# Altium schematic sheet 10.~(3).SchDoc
size 398 x 287 mm
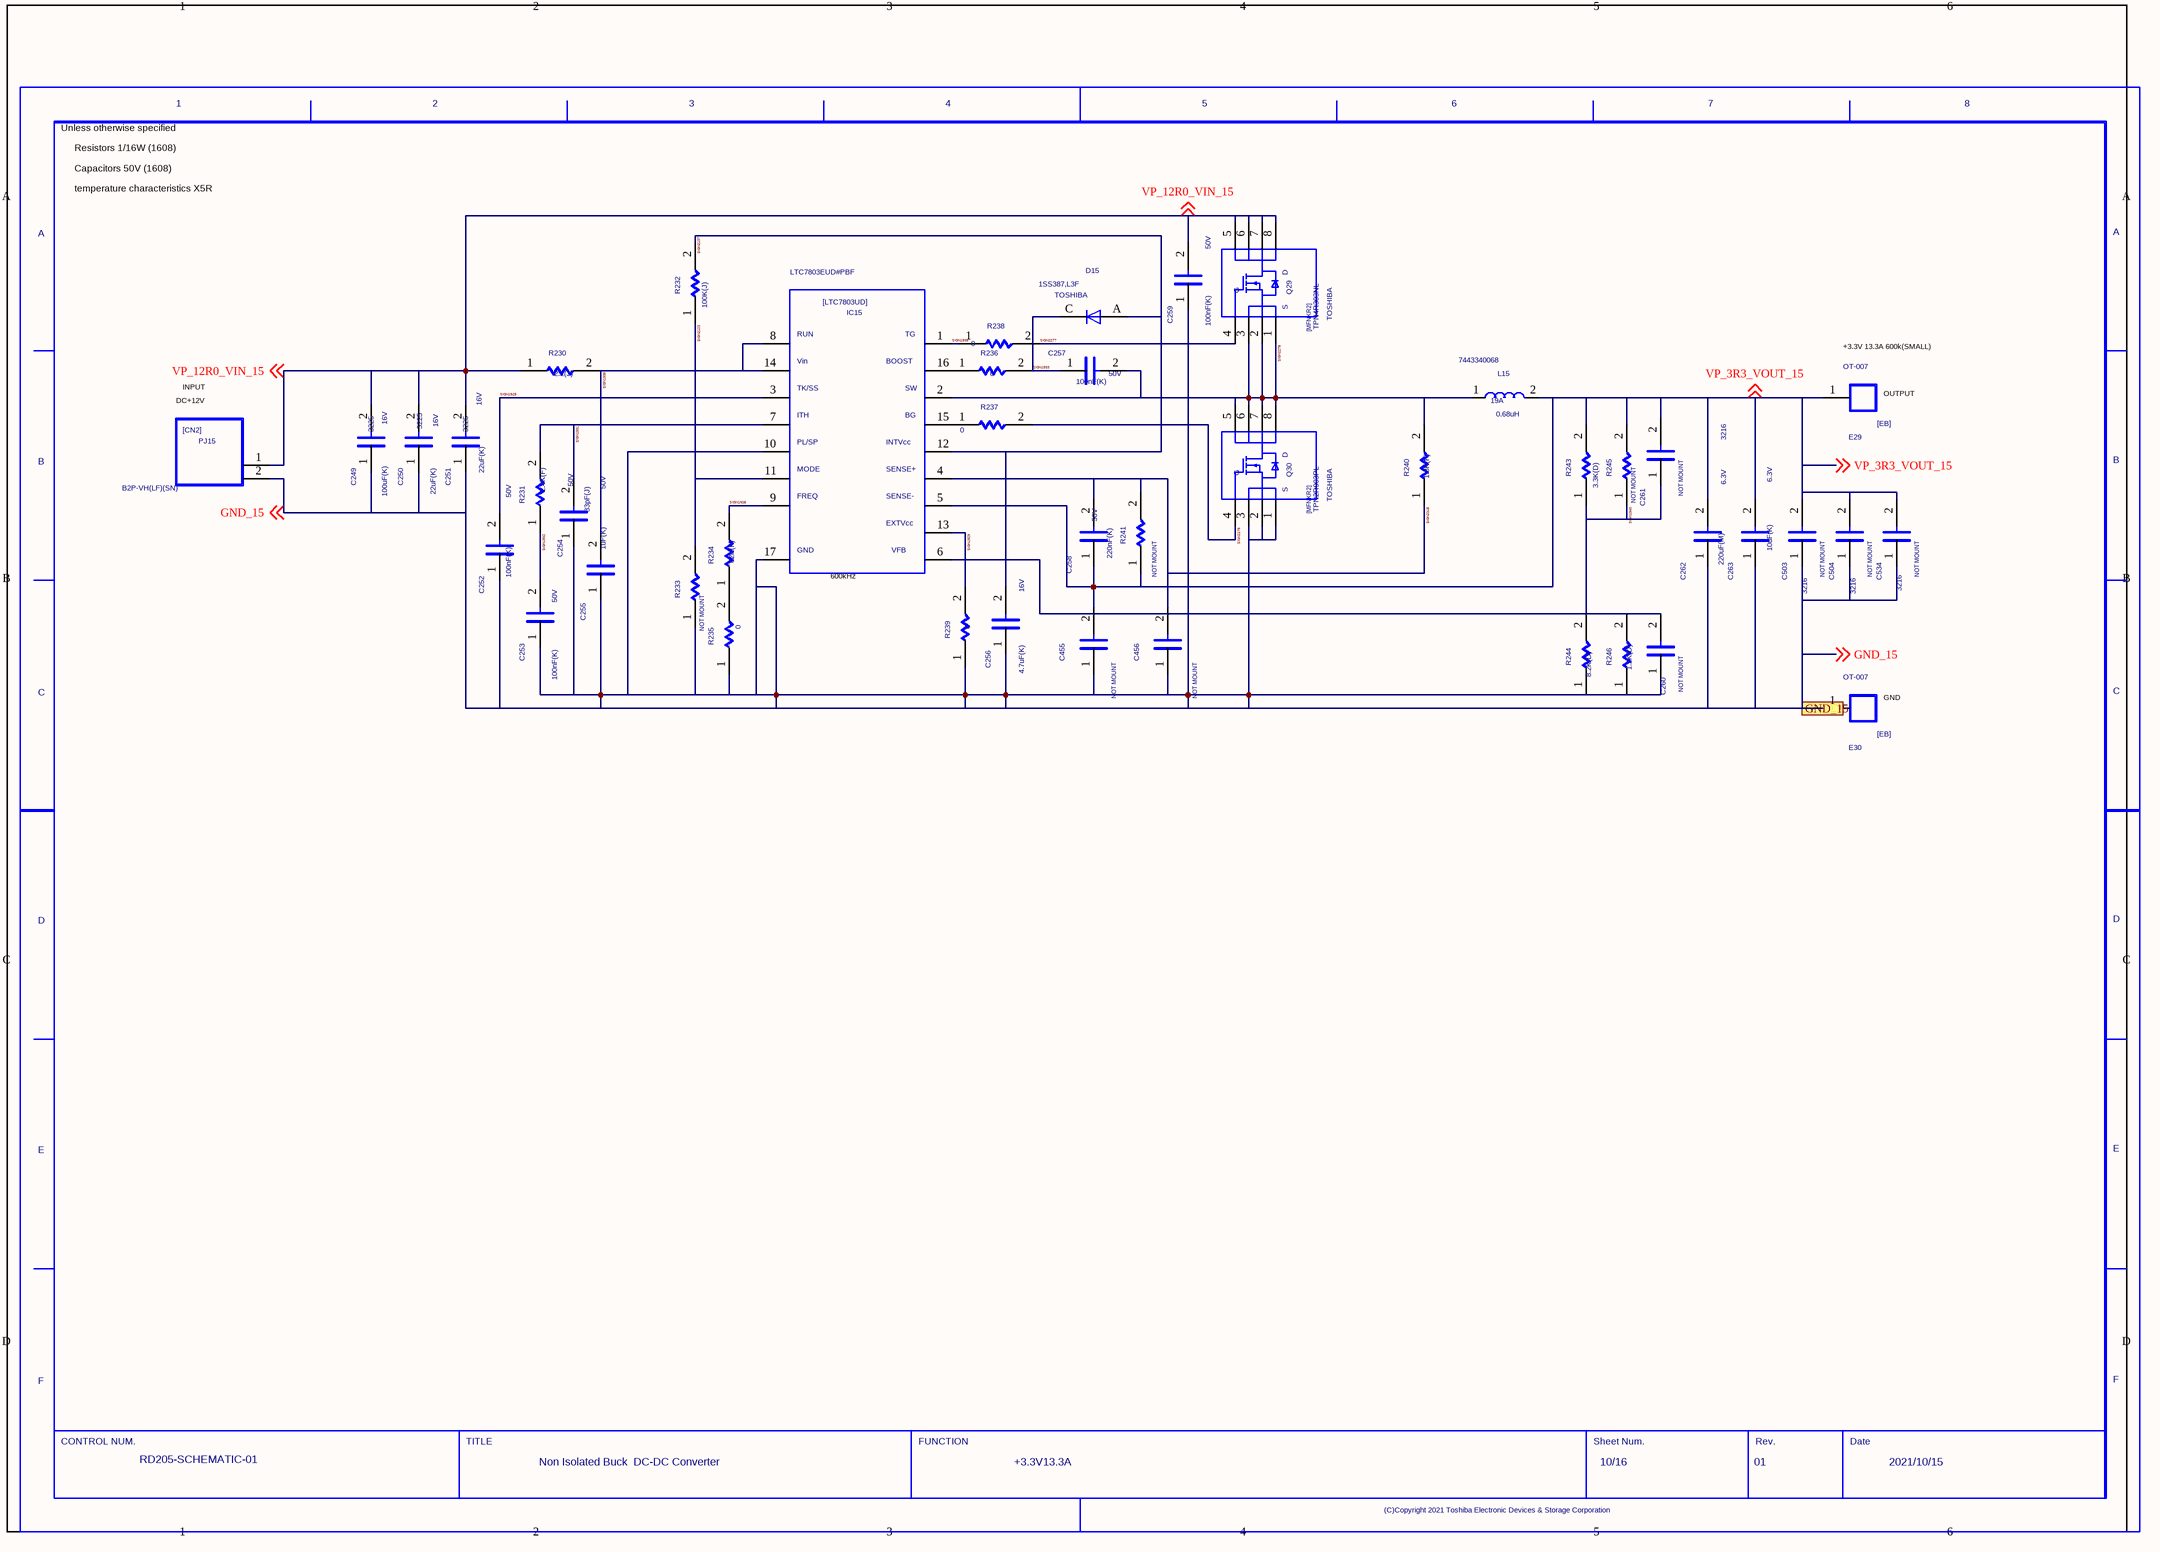
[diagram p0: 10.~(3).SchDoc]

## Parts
C249  SIZECODESMD: 3225  VAL2: 16V  VAL1: 100uF(K)  (hidden comment: C)
C250  SIZECODESMD: 3225  VAL2: 16V  VAL1: 22uF(K)  (hidden comment: C)
C251  SIZECODESMD: 3225  VAL2: 16V  VAL1: 22uF(K)  (hidden comment: C)
C252  VAL2: 50V  VAL1: 100nF(K)  (hidden comment: C)
C253  VAL2: 50V  VAL1: 100nF(K)  (hidden comment: C)
C254  VAL2: 50V  VAL1: 33pF(J)  (hidden comment: C)
C255  VAL2: 50V  VAL1: 1uF(K)  (hidden comment: C)
C256  VAL2: 16V  VAL1: 4.7uF(K)  (hidden comment: C)
C257  VAL2: 50V  VAL1: 100nF(K)  (hidden comment: C)
C258  VAL2: 50V  VAL1: 220nF(K)  (hidden comment: C)
C259  VAL2: 50V  VAL1: 100nF(K)  (hidden comment: C)
C260  NOTMOUNT: NOT MOUNT  (hidden comment: C)
C261  NOTMOUNT: NOT MOUNT  (hidden comment: C)
C262  SIZECODESMD: 3216  VAL2: 6.3V  VAL1: 220uF(M)  (hidden comment: C)
C263  VAL2: 6.3V  VAL1: 10uF(K)  (hidden comment: C)
C455  NOTMOUNT: NOT MOUNT  (hidden comment: C)
C456  NOTMOUNT: NOT MOUNT  (hidden comment: C)
C503  NOTMOUNT: NOT MOUNT  SIZECODESMD: 3216  (hidden comment: C)
C504  NOTMOUNT: NOT MOUNT  SIZECODESMD: 3216  (hidden comment: C)
C534  NOTMOUNT: NOT MOUNT  SIZECODESMD: 3216  (hidden comment: C)
D15  USERCOMPTEXT3: TOSHIBA  VAL3: 1SS387,L3F  (hidden comment: D)
E29  VAL3: OT-007  (hidden comment: EB)
E30  VAL3: OT-007  (hidden comment: EB)
IC15  VAL3: LTC7803EUD#PBF  (hidden comment: LTC7803UD)
L15  VAL3: 7443340068  VAL2: 19A  VAL1: 0.68uH  (hidden comment: L)
PJ15  VAL3: B2P-VH(LF)(SN)  (hidden comment: CN2)
Q29  USERCOMPTEXT3: TOSHIBA  VAL3: TPN4R303NL  (hidden comment: MFNKR2)
Q30  USERCOMPTEXT3: TOSHIBA  VAL3: TPN2R903PL  (hidden comment: MFNKR2)
R230  VAL1: 2.2(J)  (hidden comment: R)
R231  VAL1: 2.4K(F)  (hidden comment: R)
R232  VAL1: 100K(J)  (hidden comment: R)
R233  NOTMOUNT: NOT MOUNT  (hidden comment: R)
R234  VAL1: 62K(F)  (hidden comment: R)
R235  VAL1: 0  (hidden comment: R)
R236  VAL1: 0  (hidden comment: R)
R237  VAL1: 0  (hidden comment: R)
R238  VAL1: 0  (hidden comment: R)
R239  VAL1: 0  (hidden comment: R)
R240  VAL1: 1.8K(F)  (hidden comment: R)
R241  NOTMOUNT: NOT MOUNT  (hidden comment: R)
R243  VAL1: 3.3K(D)  (hidden comment: R)
R244  VAL1: 8.2K(D)  (hidden comment: R)
R245  NOTMOUNT: NOT MOUNT  (hidden comment: R)
R246  VAL1: 1.2K(D)  (hidden comment: R)
U?  DATE: 2021/10/15  SHEETNUMBER: 10/16  TITLE: Non Isolated Buck / DC-DC Converter  REVISION: 01  DRAWINGNUMBER: RD205-SCHEMATIC-01  FUNCTION: +3.3V13.3A  (hidden comment: WAKU_DEF100)

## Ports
GND_15

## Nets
GND_15: C249.1 C250.1 C251.1 C252.1 C253.1 C254.1 C255.1 C256.1 C259.1 C260.1 C262.1 C263.1 C455.1 C456.1 C503.1 C504.1 C534.1 E30.1 IC15.10 IC15.17 PJ15.2 Q30.1 Q30.2 Q30.3 R233.1 R235.1 R239.1 R244.1 R246.1 ; off-sheet GND_15, port GND_15
SIGN1928: C252.2 IC15.3
SIGN1929: IC15.13 R239.2
SIGN1931: C254.2 IC15.7 R231.2
SIGN1932: C253.2 R231.1
SIGN1933: C257.1 D15.C R236.2
SIGN1935: IC15.1 R238.1
SIGN1936: C255.2 IC15.8 IC15.14 R230.2
SIGN1938: IC15.9 R234.2
SIGN1940: C260.2 C261.1 IC15.6 R243.1 R244.2 R245.1 R246.2
SIGN2123: IC15.11 R232.1 R233.2
SIGN2137: C256.2 D15.A IC15.12 R232.2
SIGN2276: Q30.4 R237.2
SIGN2277: Q29.4 R238.2
SIGN2278: C257.2 IC15.2 L15.1 Q29.1 Q29.2 Q29.3 Q30.5 Q30.6 Q30.7 Q30.8 R240.2
SIGN2315: C258.2 C456.2 IC15.4 R240.1 R241.2
VP_3R3_VOUT_15: C258.1 C261.2 C262.2 C263.2 C455.2 C503.2 C504.2 C534.2 E29.1 IC15.5 L15.2 R241.1 R243.2 R245.2 ; off-sheet VP_3R3_VOUT_15
VP_12R0_VIN_15: C249.2 C250.2 C251.2 C259.2 PJ15.1 Q29.5 Q29.6 Q29.7 Q29.8 R230.1 ; off-sheet VP_12R0_VIN_15
NetIC15_15: IC15.15 R237.1
NetIC15_16: IC15.16 R236.1
NetR234_1: R234.1 R235.2

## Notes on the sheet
- Unless otherwise specified
- Resistors 1/16W (1608)
- Capacitors 50V (1608)
- temperature characteristics X5R
- DC+12V
- INPUT
- (near E29) +3.3V 13.3A 600k(SMALL)
- (near E29) OUTPUT
- (near IC15) 600kHz
- (near E30) GND

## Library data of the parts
C249 = C: SQ_PART_MODEL: CON_100n; FNPARTSNAMEG: CHIP CERAMIC CAPACITOR (3225); USEINPARTSLIST: YES; OriginalSymbolOrigin: (2540,7620); MFSOLDERINGPROP: .; TEMPCHARACTERI2: B; MFFORMINGDIVP: KC; OUMECLASSIFICATION: セラミックコンデンサ; MFMOUNTSYMBOLP: 90; CDMASTERCADCELG: DC903A; PCODE: P03276001115; FNCLASSCODEG: P03-03; MAXGCOUNT: 1; RATEDVOLTAGE: 250; COMPONENTNAME: G36030160049; OUMEMAKER: KYC 京セラ; MFPACKAGEMETHOP: S; NOMINALCAPACITA: 100n; OUMEMAKERKATAMEI: CF32W5R104K250AT; CAPACITANCETOLE: K
C250 C251 = C: SQ_PART_MODEL: CON_22u; FNPARTSNAMEG: CHIP CERAMIC CAPACITOR (3225); USEINPARTSLIST: YES; OriginalSymbolOrigin: (2540,7620); MFSOLDERINGPROP: .; TEMPCHARACTERI2: B; MFFORMINGDIVP: KC; OUMECLASSIFICATION: セラミックコンデンサ; MFMOUNTSYMBOLP: 80; CDMASTERCADCELG: DC903A; PCODE: P03043035626; FNCLASSCODEG: P03-03; MAXGCOUNT: 1; RATEDVOLTAGE: 6.3; COMPONENTNAME: G36030119054; OUMEMAKER: TYD 太陽誘電; MFPACKAGEMETHOP: S; NOMINALCAPACITA: 22u; OUMEMAKERKATAMEI: JMK325BJ226KM-T; CAPACITANCETOLE: K
C252 C253 C257 C259 = C: SQ_PART_MODEL: CON_100n; FNPARTSNAMEG: CHIP CERAMIC CAPACITOR (1608); USEINPARTSLIST: YES; OriginalSymbolOrigin: (2540,7620); MFSOLDERINGPROP: .; TEMPCHARACTERI2: B; MFFORMINGDIVP: KC; OUMECLASSIFICATION: セラミックコンデンサ; SIZECODESMD: 1608; MFMOUNTSYMBOLP: 80; CDMASTERCADCELG: C8100E; PCODE: P03B000000E4; FNCLASSCODEG: P03-03; MAXGCOUNT: 1; RATEDVOLTAGE: 16; COMPONENTNAME: GDM030000598; OUMEMAKER: MRT 村田製作所; MFPACKAGEMETHOP: S; NOMINALCAPACITA: 100n; OUMEMAKERKATAMEI: GRM188B11C104KA01C; CAPACITANCETOLE: K
C254 = C: SQ_PART_MODEL: CON_33p; FNPARTSNAMEG: CHIP CERAMIC CAPACITOR (1608); USEINPARTSLIST: YES; OriginalSymbolOrigin: (2540,7620); TOLERANCE: J; ASIMVALUE: 33P; CDMASTERCADCELG: C8100E; MFSOLDERINGPROP: .; TEMPCHARACTERI2: CH; MFFORMINGDIVP: KC; OUMECLASSIFICATION: セラミックコンデンサ; SIZECODESMD: 1608; MFMOUNTSYMBOLP: 80; PCODE: P03039307126; FNCLASSCODEG: P03-03; MAXGCOUNT: 1; RATEDVOLTAGE: 50; COMPONENTNAME: G36030011181; OUMEMAKER: KYC 京セラ; MFPACKAGEMETHOP: S; OUMEMAKERKATAMEI: CM105CH330J50AT
C255 = C: SQ_PART_MODEL: CON_1u; FNPARTSNAMEG: CHIP CERAMIC CAPACITOR (1608); USEINPARTSLIST: YES; OriginalSymbolOrigin: (2540,7620); MFSOLDERINGPROP: .; TEMPCHARACTERI2: B; MFFORMINGDIVP: KC; OUMECLASSIFICATION: セラミックコンデンサ; SIZECODESMD: 1608; MFMOUNTSYMBOLP: 80; CDMASTERCADCELG: C8100E; PCODE: P03039ACE122; FNCLASSCODEG: P03-03; MAXGCOUNT: 1; RATEDVOLTAGE: 6.3; COMPONENTNAME: G36030104159; OUMEMAKER: KYC 京セラ; MFPACKAGEMETHOP: S; NOMINALCAPACITA: 1u; OUMEMAKERKATAMEI: CM105B105K06ATN; CAPACITANCETOLE: K
C256 = C: SQ_PART_MODEL: CON_4.7u; FNPARTSNAMEG: CHIP CERAMIC CAPACITOR (1608); USEINPARTSLIST: YES; OriginalSymbolOrigin: (2540,7620); MFSOLDERINGPROP: .; TEMPCHARACTERI2: B; MFFORMINGDIVP: KC; OUMECLASSIFICATION: セラミックコンデンサ; SIZECODESMD: 1608; MFMOUNTSYMBOLP: 80; CDMASTERCADCELG: C8100E; PCODE: P03B000000MS; FNCLASSCODEG: P03-03; MAXGCOUNT: 1; RATEDVOLTAGE: 4; COMPONENTNAME: GDM030000053; OUMEMAKER: KYC 京セラ; MFPACKAGEMETHOP: S; NOMINALCAPACITA: 4.7u; OUMEMAKERKATAMEI: CM105B475M04AT; CAPACITANCETOLE: M
C258 = C: SQ_PART_MODEL: CON_220n; FNPARTSNAMEG: CHIP CERAMIC CAPACITOR (1608); PARTCOMMENT: 代表セル<KC0008> がフットプリントに登録されていません。; USEINPARTSLIST: YES; OriginalSymbolOrigin: (2540,7620); MFSOLDERINGPROP: .; TEMPCHARACTERI2: B; MFFORMINGDIVP: KC; OUMECLASSIFICATION: セラミックコンデンサ; SIZECODESMD: 1608; MFMOUNTSYMBOLP: 80; CDMASTERCADCELG: KC0008; PCODE: P03B000001L3; FNCLASSCODEG: P03-03; MAXGCOUNT: 1; RATEDVOLTAGE: 16; COMPONENTNAME: GDM030001129; OUMEMAKER: MRT 村田製作所; MFPACKAGEMETHOP: S; NOMINALCAPACITA: 220n; OUMEMAKERKATAMEI: GRM188B11C224KA01D; CAPACITANCETOLE: K
C260 C261 = C: SQ_PART_MODEL: CON_100p; FNPARTSNAMEG: CHIP CERAMIC CAPACITOR (1608); USEINPARTSLIST: YES; OriginalSymbolOrigin: (2540,7620); TOLERANCE: J; ASIMVALUE: 100P; MFSOLDERINGPROP: .; TEMPCHARACTERI2: CH; MFFORMINGDIVP: KC; OUMECLASSIFICATION: セラミックコンデンサ; SIZECODESMD: 1608; MFMOUNTSYMBOLP: 80; CDMASTERCADCELG: C8100E; PCODE: P03039177125; FNCLASSCODEG: P03-03; MAXGCOUNT: 1; RATEDVOLTAGE: 50; COMPONENTNAME: G36030011365; OUMEMAKER: KYC 京セラ; MFPACKAGEMETHOP: S; OUMEMAKERKATAMEI: CM105CH101J50AT; VAL2: 50V; VAL1: 100pF(J)
C262 = C: SQ_PART_MODEL: CON_22u; FNPARTSNAMEG: CHIP CERAMIC CAPACITOR (3216); USEINPARTSLIST: YES; OriginalSymbolOrigin: (2540,7620); MFSOLDERINGPROP: .; TEMPCHARACTERI2: B; MFFORMINGDIVP: KC; OUMECLASSIFICATION: セラミックコンデンサ; MFMOUNTSYMBOLP: 80; CDMASTERCADCELG: DC901A; PCODE: P03B0000004V; FNCLASSCODEG: P03-03; MAXGCOUNT: 1; RATEDVOLTAGE: 6.3; COMPONENTNAME: GDM030000020; OUMEMAKER: KYC 京セラ; MFPACKAGEMETHOP: S; NOMINALCAPACITA: 22u; OUMEMAKERKATAMEI: CM316B226M06AT; CAPACITANCETOLE: M
C263 = C: SQ_PART_MODEL: CON_1u; FNPARTSNAMEG: CHIP CERAMIC CAPACITOR (1608); PARTCOMMENT: 代表セル<KC0008> がフットプリントに登録されていません。; USEINPARTSLIST: YES; OriginalSymbolOrigin: (2540,7620); MFSOLDERINGPROP: .; TEMPCHARACTERI2: B; MFPACKAGEMETHOP: S; MFFORMINGDIVP: KC; MFMOUNTSYMBOLP: 80; PCODE: P03B000000ZQ; OUMECLASSIFICATION: セラミックコンデンサ; SIZECODESMD: 1608; CDMASTERCADCELG: KC0008; FNCLASSCODEG: P03-03; MAXGCOUNT: 1; RATEDVOLTAGE: 6.3; COMPONENTNAME: GDM030000202; OUMEMAKER: MRT 村田製作所; NOMINALCAPACITA: 1u; OUMEMAKERKATAMEI: GRM185B10J105KE21D; CAPACITANCETOLE: K
C455 C456 = C: SQ_PART_MODEL: CON_220n; FNPARTSNAMEG: CHIP CERAMIC CAPACITOR (1608); PARTCOMMENT: 代表セル<KC0008> がフットプリントに登録されていません。; USEINPARTSLIST: YES; OriginalSymbolOrigin: (2540,7620); MFSOLDERINGPROP: .; TEMPCHARACTERI2: B; MFFORMINGDIVP: KC; OUMECLASSIFICATION: セラミックコンデンサ; SIZECODESMD: 1608; MFMOUNTSYMBOLP: 80; CDMASTERCADCELG: KC0008; PCODE: P03B000001L3; FNCLASSCODEG: P03-03; MAXGCOUNT: 1; RATEDVOLTAGE: 16; COMPONENTNAME: GDM030001129; OUMEMAKER: MRT 村田製作所; MFPACKAGEMETHOP: S; NOMINALCAPACITA: 220n; OUMEMAKERKATAMEI: GRM188B11C224KA01D; VAL2: 16V; VAL1: 220nF(K); CAPACITANCETOLE: K
C503 C504 C534 = C: SQ_PART_MODEL: CON_22u; FNPARTSNAMEG: CHIP CERAMIC CAPACITOR (3216); USEINPARTSLIST: YES; OriginalSymbolOrigin: (2540,7620); MFSOLDERINGPROP: .; TEMPCHARACTERI2: B; MFFORMINGDIVP: KC; OUMECLASSIFICATION: セラミックコンデンサ; MFMOUNTSYMBOLP: 80; CDMASTERCADCELG: DC901A; PCODE: P03B0000004V; FNCLASSCODEG: P03-03; MAXGCOUNT: 1; RATEDVOLTAGE: 6.3; COMPONENTNAME: GDM030000020; OUMEMAKER: KYC 京セラ; MFPACKAGEMETHOP: S; NOMINALCAPACITA: 22u; OUMEMAKERKATAMEI: CM316B226M06AT; VAL2: 6.3V; VAL1: 22uF(M); CAPACITANCETOLE: M
D15 = D: FNPARTSNAMEG: DIODE; USEINPARTSLIST: YES; PARTNAME: GDM420000143; SAVEAREA0: -565,-171,12979,8058; SAVECOUNT: 1; TIME: 14:49:55; UPDATEUSER: 19870035; UPDATETIME: 14:20:16; OriginalSymbolOrigin: (5080,5080); FORWARDVOLTAGEM: 0; MAXREVERSEVOLTA: 80; COMPONENTNAME: GDM420000143_package; MFSOLDERINGPROP: .; OUMEMAKER: TSB 東芝（ＹＰＳＳ）; QUADMODEL: dummymodel; MFPACKAGEMETHOP: S; MFFORMINGDIVP: MM; MOUNTINGFORMSMD: SMD; OUMECLASSIFICATION: 小信号ダイオード; OUMEMAKERKATAMEI: 1SS387(TPH3,F); CDMASTERCADCELG: D8101D; PCODE: P42B0000008E; FNCLASSCODEG: P42-01
E29 E30 = EB: FNPARTSNAMEG: TERMINAL; USEINPARTSLIST: YES; PARTNAME: 5P9L1232P001; OUMEPARTTYPE: TB; OriginalSymbolOrigin: (2540,12700); COMPONENTNAME: 5P9L1232P001_package; MAXGCOUNT: 1; MFSOLDERINGPROP: .; OUMEMAKER: オサダ; QUADMODEL: dummymodel; MFPACKAGEMETHOP: I; MFFORMINGDIVP: OD; OUMECLASSIFICATION: 端子台、端子板; CDMASTERCADCELG: DE0009; KIND: PBS; PCODE: P29045001117; TERMINALSTYLE: SC; FNCLASSCODEG: P29-01
IC15 = LTC7803UD: USEINPARTSLIST: YES; SAVECOUNT: 29; SAVEAREA0: -53177,0,89020,58420; TIME: 16:14:14; UPDATEUSER: q91866sr; UPDATETIME: 13:15:36; OriginalSymbolOrigin: (5080,55880); MAXGCOUNT: 1; COMPONENTNAME: LTC7803UD_LTC7803UD; OUMEMAKER: ANALOG DEVICES
L15 = L: USEINPARTSLIST: YES; OriginalSymbolOrigin: (2540,5080); MAXGCOUNT: 1; COMPONENTNAME: L_L; OUMEMAKER: WURTH
PJ15 = CN2: FNPARTSNAMEG: 3.96PITCH NYLON CONNECTOR; USEINPARTSLIST: YES; PARTNAME: G36220114012; OUMEPARTTYPE: CN; OriginalSymbolOrigin: (2540,15240); MAXGCOUNT: 1; RATEDCURRENT: 7; COMPONENTNAME: G36220114012_package; MFSOLDERINGPROP: .; OUMEMAKER: JST 日本圧着端子製造; NUMBEROFCONTACT: 2; QUADMODEL: dummymodel; MFPACKAGEMETHOP: I; MFFORMINGDIVP: CU; CONTACTPITCH: 3.96m; OUMEMAKERKATAMEI: B2P-VH; CDMASTERCADCELG: DPJ514; PCODE: P22346001114; TERMINALSTYLE: PW; FNCLASSCODEG: P22-10
Q29 Q30 = MFNKR2: USEINPARTSLIST: YES; PARTNAME: TPN1R603PL; SAVEAREA0: -9199,-39,32138,22820; TIME: 18:57:44; UPDATEUSER: q91866sr; UPDATETIME: 12:36:02; SAVECOUNT: 10; OriginalSymbolOrigin: (5080,20320); MAXGCOUNT: 1; COMPONENTNAME: MFNKR2_MFNKR2
R230 = R: SQ_PART_MODEL: RES_2.2; FNPARTSNAMEG: CHIP RESISTOR (1608); USEINPARTSLIST: YES; OriginalSymbolOrigin: (5080,5080); TOLERANCE: J; ASIMVALUE: 2.2; MAXGCOUNT: 1; COMPONENTNAME: G36010011507; MFSOLDERINGPROP: .; OUMEMAKER: NAE 松下電子部品; MFPACKAGEMETHOP: S; MFFORMINGDIVP: KC; MOUNTINGFORMSMD: SMD; OUMECLASSIFICATION: 表面実装用固定抵抗器; MFMOUNTSYMBOLP: 80; POWERRATING: 63m; OUMEMAKERKATAMEI: ERJ3GEYJ2R2V; NUMBEROFELEMENT: 0; VAL2: 62.5mW; CDMASTERCADCELG: DR802R; PCODE: P01042157622; FNCLASSCODEG: P01-08
R231 = R: SQ_PART_MODEL: RES_2.4K; FNPARTSNAMEG: CHIP RESISTOR (1608); USEINPARTSLIST: YES; OriginalSymbolOrigin: (5080,5080); TOLERANCE: F; ASIMVALUE: 2.4K; MAXGCOUNT: 1; COMPONENTNAME: G36010104094; MFSOLDERINGPROP: .; OUMEMAKER: KAM 釜屋電機; MFPACKAGEMETHOP: S; MFFORMINGDIVP: KC; MOUNTINGFORMSMD: SMD; OUMECLASSIFICATION: 表面実装用固定抵抗器; MFMOUNTSYMBOLP: 80; POWERRATING: 63m; OUMEMAKERKATAMEI: RMC1/16-242FTP; NUMBEROFELEMENT: 0; VAL2: 62.5mW; CDMASTERCADCELG: DR802R; PCODE: P01042166327; FNCLASSCODEG: P01-08
R232 = R: SQ_PART_MODEL: RES_100K; FNPARTSNAMEG: CHIP RESISTOR (1608); USEINPARTSLIST: YES; OriginalSymbolOrigin: (5080,5080); TOLERANCE: J; ASIMVALUE: 100K; MFSOLDERINGPROP: .; MFPACKAGEMETHOP: S; MFFORMINGDIVP: KC; MOUNTINGFORMSMD: SMD; MFMOUNTSYMBOLP: 80; NUMBEROFELEMENT: 0; PCODE: P01042047220; MAXGCOUNT: 1; COMPONENTNAME: G36010011057; OUMEMAKER: HDK 北陸電気工業; OUMECLASSIFICATION: 表面実装用固定抵抗器; POWERRATING: 63m; OUMEMAKERKATAMEI: CR1/16 104JV; VAL2: 62.5mW; CDMASTERCADCELG: DR802R; FNCLASSCODEG: P01-08
R233 = R: SQ_PART_MODEL: RES_10; FNPARTSNAMEG: CHIP RESISTOR (1608); USEINPARTSLIST: YES; OriginalSymbolOrigin: (5080,5080); TOLERANCE: F; ASIMVALUE: 10; MFSOLDERINGPROP: .; MFPACKAGEMETHOP: S; MFFORMINGDIVP: KC; MOUNTINGFORMSMD: SMD; MFMOUNTSYMBOLP: 80; NUMBEROFELEMENT: 0; PCODE: P01042036620; MAXGCOUNT: 1; COMPONENTNAME: G36010104063; OUMEMAKER: NAE 松下電子部品; OUMECLASSIFICATION: 表面実装用固定抵抗器; POWERRATING: 63m; OUMEMAKERKATAMEI: ERJ3GEYF100V; VAL2: 62.5mW; VAL1: 10(F); CDMASTERCADCELG: DR802R; FNCLASSCODEG: P01-08
R234 = R: SQ_PART_MODEL: RES_62K; FNPARTSNAMEG: CHIP RESISTOR (1608); USEINPARTSLIST: YES; OriginalSymbolOrigin: (5080,5080); MAXGCOUNT: 1; COMPONENTNAME: GDM010001037; MFSOLDERINGPROP: .; OUMEMAKER: NAE 松下電子部品; MFPACKAGEMETHOP: S; MFFORMINGDIVP: KC; MOUNTINGFORMSMD: SMD; OUMECLASSIFICATION: 表面実装用固定抵抗器; RESISTANCETOLER: F; MFMOUNTSYMBOLP: 80; POWERRATING: 63m; OUMEMAKERKATAMEI: ERJ3GEYF623V; NOMINALRESISTAN: 62K; NUMBEROFELEMENT: 0; VAL2: 62.5mW; CDMASTERCADCELG: DR802R; PCODE: P01042441622; FNCLASSCODEG: P01-08
R235 = R: SQ_PART_MODEL: RES_160K; FNPARTSNAMEG: CHIP RESISTOR (1608); USEINPARTSLIST: YES; OriginalSymbolOrigin: (5080,5080); MAXGCOUNT: 1; COMPONENTNAME: G51011061108; MFSOLDERINGPROP: .; OUMEMAKER: HDK 北陸電気工業; MFPACKAGEMETHOP: S; MFFORMINGDIVP: KC; MOUNTINGFORMSMD: SMD; OUMECLASSIFICATION: 表面実装用固定抵抗器; RESISTANCETOLER: F; MFMOUNTSYMBOLP: 80; POWERRATING: 63m; OUMEMAKERKATAMEI: CR1/16 164FV; NOMINALRESISTAN: 160K; VAL2: 62.5mW; CDMASTERCADCELG: DR802R; PCODE: P01042125225; FNCLASSCODEG: P01-08
R236 R239 = R: SQ_PART_MODEL: RES_10; FNPARTSNAMEG: CHIP RESISTOR (1608); USEINPARTSLIST: YES; OriginalSymbolOrigin: (5080,5080); TOLERANCE: F; ASIMVALUE: 10; MFSOLDERINGPROP: .; MFPACKAGEMETHOP: S; MFFORMINGDIVP: KC; MOUNTINGFORMSMD: SMD; MFMOUNTSYMBOLP: 80; PCODE: P01042036620; MAXGCOUNT: 1; COMPONENTNAME: G36010104063; OUMEMAKER: NAE 松下電子部品; OUMECLASSIFICATION: 表面実装用固定抵抗器; POWERRATING: 63m; OUMEMAKERKATAMEI: ERJ3GEYF100V; VAL2: 62.5mW; CDMASTERCADCELG: DR802R; FNCLASSCODEG: P01-08
R237 R238 = R: SQ_PART_MODEL: RES_10; FNPARTSNAMEG: CHIP RESISTOR (2012); USEINPARTSLIST: YES; OriginalSymbolOrigin: (5080,5080); MAXGCOUNT: 1; TOLERANCE: F; COMPONENTNAME: 5P9L1083P100; MFSOLDERINGPROP: .; OUMEMAKER: 北陸電気工業; MFPACKAGEMETHOP: S; MFFORMINGDIVP: KC; MOUNTINGFORMSMD: SMD; OUMECLASSIFICATION: 表面実装用固定抵抗器; ASIMVALUE: 10; MFMOUNTSYMBOLP: 90; POWERRATING: 100m; OUMEMAKERKATAMEI: CR1/10 100FV Pb(F); VAL2: 125mW; CDMASTERCADCELG: DR910A; PCODE: P01043091222; FNCLASSCODEG: P01-08
R240 = R: SQ_PART_MODEL: RES_1.8K; FNPARTSNAMEG: CHIP RESISTOR (1608); USEINPARTSLIST: YES; OriginalSymbolOrigin: (5080,5080); TOLERANCE: F; ASIMVALUE: 1.8K; MAXGCOUNT: 1; COMPONENTNAME: G36010104056; MFSOLDERINGPROP: .; OUMEMAKER: HDK 北陸電気工業; MFPACKAGEMETHOP: S; MFFORMINGDIVP: KC; MOUNTINGFORMSMD: SMD; OUMECLASSIFICATION: 表面実装用固定抵抗器; MFMOUNTSYMBOLP: 80; POWERRATING: 63m; OUMEMAKERKATAMEI: CR1/16 182FV; NUMBEROFELEMENT: 0; VAL2: 62.5mW; CDMASTERCADCELG: DR802R; PCODE: P01042030222; FNCLASSCODEG: P01-08
R241 = R: SQ_PART_MODEL: RES_22K; FNPARTSNAMEG: CHIP RESISTOR (1608); USEINPARTSLIST: YES; OriginalSymbolOrigin: (5080,5080); MAXGCOUNT: 1; COMPONENTNAME: G36010027089; OUMEMAKER: KOA ＫＯＡ; MOUNTINGFORMSMD: SMD; OUMECLASSIFICATION: 表面実装用固定抵抗器; RESISTANCETOLER: F; POWERRATING: 63m; OUMEMAKERKATAMEI: RK73H1JTD2202F; NOMINALRESISTAN: 22K; CDMASTERCADCELG: DR802R; MFSOLDERINGPROP: .; MFPACKAGEMETHOP: S; MFFORMINGDIVP: KC; MFMOUNTSYMBOLP: 80; NUMBEROFELEMENT: 0; VAL2: 62.5mW; VAL1: 22K(F); PCODE: P01042207426; FNCLASSCODEG: P01-08
R243 = R: SQ_PART_MODEL: RES_3.3K; FNPARTSNAMEG: CHIP RESISTOR (1608); USEINPARTSLIST: YES; OriginalSymbolOrigin: (5080,5080); MAXGCOUNT: 1; COMPONENTNAME: G36010014485; MFSOLDERINGPROP: .; OUMEMAKER: SSM 進工業; MFPACKAGEMETHOP: S; MFFORMINGDIVP: KC; MOUNTINGFORMSMD: SMD; OUMECLASSIFICATION: 表面実装用固定抵抗器; RESISTANCETOLER: D; MFMOUNTSYMBOLP: 80; POWERRATING: 63m; OUMEMAKERKATAMEI: RR0816P-332-D; NOMINALRESISTAN: 3.3K; NUMBEROFELEMENT: 0; VAL2: 62.5mW; CDMASTERCADCELG: DR802R; PCODE: P01042249822; FNCLASSCODEG: P01-08
R244 = R: ICX_PART_MODEL: RES_8.2K; FNPARTSNAMEG: CHIP RESISTOR (1608); OriginalSymbolOrigin: (5080,5080); FNCLASSCODEG: P01-08; PCODE: P01117051114; CDMASTERCADCELG: DR802R; USEWITHSCHEMA: YES; VAL2: 62.5mW; NUMBEROFELEMENT: 0; NOMINALRESISTAN: 8.2K; OUMEMAKERKATAMEI: RK73G1JTD822D; POWERRATING: 63m; MFMOUNTSYMBOLP: 80; RESISTANCETOLER: D; FUNCTION: G36010129479; OUMECLASSIFICATION: 表面実装用固定抵抗器; MOUNTINGFORMSMD: SMD; MFFORMINGDIVP: KC; MFPACKAGEMETHOP: S; OUMEMAKER: KOA ＫＯＡ; MFSOLDERINGPROP: .; MAXGCOUNT: 1
R245 = R: SQ_PART_MODEL: RES_3.3K; FNPARTSNAMEG: CHIP RESISTOR (1608); USEINPARTSLIST: YES; OriginalSymbolOrigin: (5080,5080); TOLERANCE: F; ASIMVALUE: 3.3K; MAXGCOUNT: 1; COMPONENTNAME: G36010027027; MFSOLDERINGPROP: .; OUMEMAKER: ROH ロー・; MFPACKAGEMETHOP: S; MFFORMINGDIVP: KC; MOUNTINGFORMSMD: SMD; OUMECLASSIFICATION: 表面実装用固定抵抗器; MFMOUNTSYMBOLP: 80; POWERRATING: 63m; OUMEMAKERKATAMEI: MCR03EZPFX3301; NUMBEROFELEMENT: 0; VAL2: 62.5mW; VAL1: 3.3K(F); CDMASTERCADCELG: DR802R; PCODE: P01042250729; FNCLASSCODEG: P01-08
R246 = R: ICX_PART_MODEL: RES_1.2K; FNPARTSNAMEG: CHIP RESISTOR (1608); OriginalSymbolOrigin: (5080,5080); FNCLASSCODEG: P01-08; PCODE: P01117031116; CDMASTERCADCELG: DR802R; USEWITHSCHEMA: YES; VAL2: 62.5mW; NUMBEROFELEMENT: 0; NOMINALRESISTAN: 1.2K; OUMEMAKERKATAMEI: RK73G1JTD122D; POWERRATING: 63m; MFMOUNTSYMBOLP: 80; RESISTANCETOLER: D; FUNCTION: G36010129271; OUMECLASSIFICATION: 表面実装用固定抵抗器; MOUNTINGFORMSMD: SMD; MFFORMINGDIVP: KC; MFPACKAGEMETHOP: S; OUMEMAKER: KOA ＫＯＡ; MFSOLDERINGPROP: .; MAXGCOUNT: 1
U? = WAKU_DEF100: PLOTTIME: HH:MM; SAVEAREA0: 330961,54,387907,31546; TIME: 19:23:07; UPDATEUSER: t5459927; UPDATETIME: 15:33:41; SAVECOUNT: 6; OriginalSymbolOrigin: (10160,284480); DESIGNED: ***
